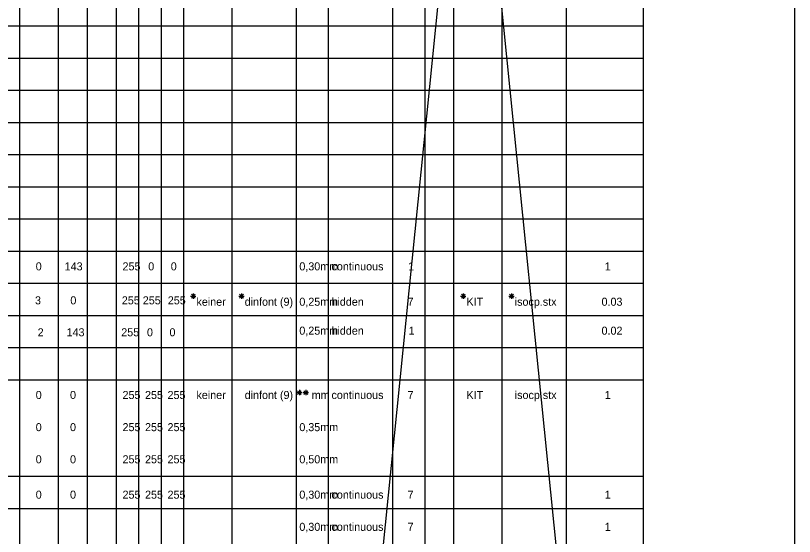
# Model space of a CAD drawing. Extents: x -29 to 48, y -113 to 16.
# Drawn here: x 23.27 to 47.5, y -79.87 to -63.68 of the extents above; entities that cross this region are included whole.
import ezdxf

# ---------------------------------------------------------------- set-up
doc = ezdxf.new("R2010")
doc.units = 0
doc.layers.add('Default', color=7, linetype='Continuous')
doc.layers.add('Default_DWG', color=7, linetype='Continuous')

msp = doc.modelspace()

# ---------------------------------------------------------------- linework, layer by layer
at = {"layer": 'Default'}
for p, q in [((32, 0), (32, -96)), ((42.8, 0), (32, -107)), ((42.8, -107), (32, 0)), ((42.8, 0), (42.8, -107)), ((47.5, 0), (47.5, -107)), ((23.4, -0.7), (23.4, -89)), ((24.6, -0.7), (24.6, -89)), ((25.5, -0.7), (25.5, -89)), ((26.4, -0.7), (26.4, -89)), ((28.5, -0.7), (28.5, -96)), ((30, -0.7), (30, -96)), ((27.1, -1.5), (27.1, -89)), ((27.8, -1.5), (27.8, -89)), ((0, -64), (32, -64)), ((0, -65), (32, -65)), ((0, -66), (32, -66)), ((0, -67), (32, -67)), ((0, -68), (32, -68)), ((0, -69), (32, -69)), ((0, -70), (32, -70)), ((0, -71), (32, -71)), ((0, -72), (32, -72)), ((28.716, -72.4), (28.884, -72.4)), ((28.741, -72.341), (28.859, -72.459)), ((28.859, -72.341), (28.741, -72.459)), ((28.8, -72.316), (28.8, -72.484)), ((30.216, -72.4), (30.384, -72.4)), ((30.241, -72.341), (30.359, -72.459)), ((30.359, -72.341), (30.241, -72.459)), ((30.3, -72.316), (30.3, -72.484)), ((0, -73), (32, -73)), ((0, -74), (32, -74)), ((0, -75), (32, -75)), ((0, -78), (32, -78)), ((0, -79), (32, -79))]:
    msp.add_line(p, q, dxfattribs=at)
at = {"layer": 'Default_DWG'}
for p, q in [((40.4, 0), (40.4, -96)), ((33, -0.7), (33, -96)), ((35, -0.7), (35, -96)), ((36, -0.7), (36, -96)), ((36.9, -0.7), (36.9, -96)), ((38.4, -0.7), (38.4, -96)), ((32, -64), (42.8, -64)), ((32, -65), (42.8, -65)), ((32, -66), (42.8, -66)), ((32, -67), (42.8, -67)), ((32, -68), (42.8, -68)), ((32, -69), (42.8, -69)), ((32, -70), (42.8, -70)), ((32, -71), (42.8, -71)), ((32, -72), (42.8, -72)), ((37.116, -72.4), (37.284, -72.4)), ((37.141, -72.341), (37.259, -72.459)), ((37.259, -72.341), (37.141, -72.459)), ((37.2, -72.316), (37.2, -72.484)), ((38.616, -72.4), (38.784, -72.4)), ((38.641, -72.341), (38.759, -72.459)), ((38.759, -72.341), (38.641, -72.459)), ((38.7, -72.316), (38.7, -72.484)), ((32, -73), (42.8, -73)), ((32, -74), (42.8, -74)), ((32, -75), (42.8, -75)), ((32.041, -75.341), (32.159, -75.459)), ((32.159, -75.341), (32.041, -75.459)), ((32.1, -75.316), (32.1, -75.484)), ((32.241, -75.341), (32.359, -75.459)), ((32.359, -75.341), (32.241, -75.459)), ((32.3, -75.316), (32.3, -75.484)), ((32.016, -75.4), (32.184, -75.4)), ((32.216, -75.4), (32.384, -75.4)), ((32, -78), (42.8, -78)), ((32, -79), (42.8, -79))]:
    msp.add_line(p, q, dxfattribs=at)

# ---------------------------------------------------------------- texts
at = {"layer": 'Default'}
for s, p in [('0', (23.9, -71.6)), ('143', (24.8, -71.6)), ('255', (26.6, -71.6)), ('0', (27.4, -71.6)), ('0', (28.1, -71.6)), ('3', (23.877, -72.657)), ('0', (24.977, -72.657)), ('255', (26.578, -72.657)), ('255', (27.23, -72.657)), ('255', (28.008, -72.657)), ('keiner', (28.9, -72.7)), ('dinfont (9)', (30.4, -72.7)), ('2', (23.96, -73.65)), ('143', (24.86, -73.65)), ('255', (26.56, -73.65)), ('0', (27.36, -73.65)), ('0', (28.06, -73.65)), ('keiner', (28.9, -75.6)), ('dinfont (9)', (30.4, -75.6)), ('0', (23.9, -75.6)), ('0', (24.967, -75.6)), ('255', (26.6, -75.6)), ('255', (27.3, -75.6)), ('255', (28, -75.6)), ('0', (23.9, -76.6)), ('0', (24.967, -76.6)), ('255', (26.6, -76.6)), ('255', (27.3, -76.6)), ('255', (28, -76.6)), ('0', (23.9, -77.6)), ('0', (24.967, -77.6)), ('255', (26.6, -77.6)), ('255', (27.3, -77.6)), ('255', (28, -77.6)), ('0', (23.9, -78.7)), ('0', (24.967, -78.7)), ('255', (26.6, -78.7)), ('255', (27.3, -78.7)), ('255', (28, -78.7))]:
    msp.add_text(s, height=0.25, dxfattribs=at).set_placement(p)
at = {"layer": 'Default_DWG'}
for s, p in [('0,30mm', (32.1, -71.6)), ('continuous', (33.1, -71.6)), ('1', (35.484, -71.6)), ('1', (41.6, -71.6)), ('hidden', (33.1, -72.7)), ('isocp.stx', (38.8, -72.7)), ('0,25mm', (32.1, -72.7)), ('7', (35.467, -72.7)), ('KIT', (37.3, -72.7)), ('0.03', (41.5, -72.7)), ('0,25mm', (32.1, -73.6)), ('hidden', (33.1, -73.6)), ('1', (35.5, -73.6)), ('0.02', (41.5, -73.6)), ('continuous', (33.1, -75.6)), ('isocp.stx', (38.8, -75.6)), ('  mm', (32.3, -75.6)), ('7', (35.467, -75.6)), ('KIT', (37.3, -75.6)), ('1', (41.6, -75.6)), ('0,35mm', (32.1, -76.6)), ('0,50mm', (32.1, -77.6)), ('0,30mm', (32.1, -78.7)), ('continuous', (33.1, -78.7)), ('7', (35.467, -78.7)), ('1', (41.6, -78.7)), ('0,30mm', (32.1, -79.7)), ('continuous', (33.1, -79.7)), ('7', (35.467, -79.7)), ('1', (41.6, -79.7))]:
    msp.add_text(s, height=0.25, dxfattribs=at).set_placement(p)

doc.saveas('drawing.dxf')
